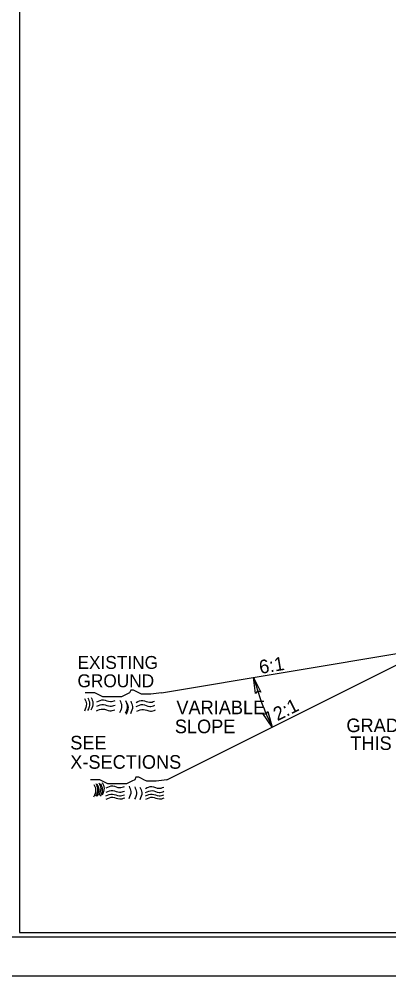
# Model space of a CAD drawing. Extents: x 2294370 to 2294957, y 719276 to 719941.
# Drawn here: x 2294488.5 to 2294531, y 719276.3 to 719386.3 of the extents above; entities that cross this region are included whole.
import ezdxf

# ---------------------------------------------------------------- set-up
doc = ezdxf.new("R2010")
doc.units = 0
for name, color, linetype in [('Old_Level_1', 7, 'Continuous'), ('Old_Level_11', 7, 'Continuous'), ('Old_Level_2', 7, 'Continuous'), ('Sheet Cutting Line CELL', 7, 'Continuous'), ('Sheet Plot Border Inside CELL', 7, 'Continuous'), ('Sheet Plot Border Outside CELL', 7, 'Continuous'), ('Sheet Typical CELL', 7, 'Continuous'), ('Typical Hinge Slope Arterial CELL', 7, 'Continuous')]:
    doc.layers.add(name, color=color, linetype=linetype)

msp = doc.modelspace()

# ---------------------------------------------------------------- linework, layer by layer
at = {"layer": 'Old_Level_11'}
for points in [[(2294515.69, 719308.79), (2294515.48, 719310.65), (2294516.31, 719308.96), (2294515.93, 719309.1)], [(2294517.12, 719306.75), (2294517.62, 719304.95), (2294516.53, 719306.49), (2294516.93, 719306.42)]]:
    msp.add_lwpolyline(points, close=True, dxfattribs=at)
at = {"layer": 'Old_Level_2'}
for points in [[(2294496.03, 719308.23), (2294496.24, 719307.61), (2294496.01, 719306.78)], [(2294496.03, 719308.23), (2294496.24, 719307.61), (2294496.01, 719306.78)], [(2294496.4, 719308.3), (2294496.61, 719307.68), (2294496.38, 719306.85)], [(2294496.4, 719308.3), (2294496.61, 719307.68), (2294496.38, 719306.85)], [(2294496.79, 719308.34), (2294497, 719307.72), (2294496.77, 719306.9)], [(2294496.79, 719308.34), (2294497, 719307.72), (2294496.77, 719306.9)], [(2294497.45, 719307.85), (2294498.2, 719308.07), (2294499, 719307.87), (2294499.57, 719308)], [(2294497.45, 719307.85), (2294498.2, 719308.07), (2294499, 719307.87), (2294499.57, 719308)], [(2294500.08, 719308.03), (2294500.29, 719307.41), (2294500.06, 719306.59)], [(2294500.08, 719308.03), (2294500.29, 719307.41), (2294500.06, 719306.59)], [(2294500.74, 719307.98), (2294500.95, 719307.36), (2294500.72, 719306.54)], [(2294500.74, 719307.98), (2294500.95, 719307.36), (2294500.72, 719306.54)], [(2294500.83, 719307.84), (2294501.04, 719307.22), (2294500.81, 719306.4)], [(2294501.34, 719307.93), (2294501.55, 719307.3), (2294501.32, 719306.48)], [(2294501.96, 719307.78), (2294502.72, 719308), (2294503.51, 719307.79), (2294504.08, 719307.92)], [(2294501.96, 719307.78), (2294502.72, 719308), (2294503.51, 719307.79), (2294504.08, 719307.92)], [(2294497.39, 719306.8), (2294498.14, 719307.02), (2294498.94, 719306.82), (2294499.51, 719306.94)], [(2294497.39, 719306.8), (2294498.14, 719307.02), (2294498.94, 719306.82), (2294499.51, 719306.94)], [(2294497.45, 719307.33), (2294498.2, 719307.54), (2294498.99, 719307.34), (2294499.56, 719307.47)], [(2294497.45, 719307.33), (2294498.2, 719307.54), (2294498.99, 719307.34), (2294499.56, 719307.47)], [(2294501.98, 719307.31), (2294502.74, 719307.53), (2294503.53, 719307.32), (2294504.1, 719307.45)], [(2294501.98, 719307.31), (2294502.74, 719307.53), (2294503.53, 719307.32), (2294504.1, 719307.45)], [(2294502.06, 719306.77), (2294502.81, 719306.98), (2294503.61, 719306.78), (2294504.18, 719306.91)], [(2294502.06, 719306.77), (2294502.81, 719306.98), (2294503.61, 719306.78), (2294504.18, 719306.91)], [(2294497.1, 719298.34), (2294497.31, 719297.72), (2294497.08, 719296.89)], [(2294497.32, 719298.44), (2294497.53, 719297.82), (2294497.3, 719297)], [(2294497.46, 719298.41), (2294497.67, 719297.78), (2294497.45, 719296.96)], [(2294497.68, 719298.52), (2294497.89, 719297.89), (2294497.66, 719297.07)], [(2294497.85, 719298.45), (2294498.07, 719297.83), (2294497.84, 719297)], [(2294498.07, 719298.56), (2294498.28, 719297.93), (2294498.05, 719297.11)], [(2294498.52, 719297.96), (2294499.27, 719298.18), (2294500.07, 719297.98), (2294500.64, 719298.11)], [(2294498.52, 719297.96), (2294499.27, 719298.18), (2294500.07, 719297.98), (2294500.64, 719298.11)], [(2294501.15, 719298.14), (2294501.36, 719297.52), (2294501.13, 719296.7)], [(2294501.15, 719298.14), (2294501.36, 719297.52), (2294501.13, 719296.7)], [(2294501.8, 719298.09), (2294502.01, 719297.47), (2294501.79, 719296.64)], [(2294501.8, 719298.09), (2294502.01, 719297.47), (2294501.79, 719296.64)], [(2294502.41, 719298.04), (2294502.62, 719297.41), (2294502.39, 719296.59)], [(2294502.41, 719298.04), (2294502.62, 719297.41), (2294502.39, 719296.59)], [(2294503.03, 719297.89), (2294503.78, 719298.11), (2294504.58, 719297.9), (2294505.15, 719298.03)], [(2294503.03, 719297.89), (2294503.78, 719298.11), (2294504.58, 719297.9), (2294505.15, 719298.03)], [(2294498.49, 719297.02), (2294499.24, 719297.24), (2294500.04, 719297.04), (2294500.61, 719297.17)], [(2294498.49, 719297.02), (2294499.24, 719297.24), (2294500.04, 719297.04), (2294500.61, 719297.17)], [(2294498.51, 719297.44), (2294499.27, 719297.65), (2294500.06, 719297.45), (2294500.63, 719297.58)], [(2294498.51, 719297.44), (2294499.27, 719297.65), (2294500.06, 719297.45), (2294500.63, 719297.58)], [(2294498.53, 719296.66), (2294499.28, 719296.88), (2294500.08, 719296.68), (2294500.65, 719296.8)], [(2294503.05, 719297.42), (2294503.8, 719297.64), (2294504.6, 719297.43), (2294505.17, 719297.56)], [(2294503.05, 719297.42), (2294503.8, 719297.64), (2294504.6, 719297.43), (2294505.17, 719297.56)], [(2294503.05, 719297.02), (2294503.8, 719297.24), (2294504.6, 719297.04), (2294505.17, 719297.17)], [(2294503.05, 719297.02), (2294503.8, 719297.24), (2294504.6, 719297.04), (2294505.17, 719297.17)], [(2294503.09, 719296.66), (2294503.84, 719296.88), (2294504.64, 719296.68), (2294505.21, 719296.8)]]:
    msp.add_spline(points, degree=3, dxfattribs=at)
at = {"layer": 'Sheet Cutting Line CELL'}
msp.add_line((2294455.16, 719276.34), (2294791.96, 719276.34), dxfattribs=at)
at = {"layer": 'Sheet Plot Border Inside CELL'}
msp.add_lwpolyline([(2294791.06, 719491.85), (2294457.76, 719491.85), (2294457.76, 719280.83), (2294791.06, 719280.83)], close=True, dxfattribs=at)
at = {"layer": 'Sheet Plot Border Outside CELL'}
for points in [[(2294455.16, 719276.34), (2294791.96, 719276.34), (2294791.96, 719496.34), (2294455.16, 719496.34)], [(2294791.96, 719496.34), (2294455.16, 719496.34), (2294455.16, 719276.34), (2294791.96, 719276.34)]]:
    msp.add_lwpolyline(points, close=True, dxfattribs=at)
at = {"layer": 'Sheet Typical CELL'}
msp.add_line((2294488.56, 719281.34), (2294488.56, 719281.34), dxfattribs=at)
msp.add_line((2294488.56, 719281.34), (2294488.56, 719281.34), dxfattribs=at)
msp.add_line((2294488.56, 719281.34), (2294488.56, 719281.34), dxfattribs=at)
msp.add_line((2294488.56, 719281.34), (2294488.56, 719281.34), dxfattribs=at)
msp.add_line((2294488.56, 719281.34), (2294488.56, 719281.34), dxfattribs=at)
msp.add_line((2294488.56, 719281.34), (2294488.56, 719281.34), dxfattribs=at)
msp.add_lwpolyline([(2294788.56, 719491.34), (2294488.56, 719491.34), (2294488.56, 719281.34), (2294788.56, 719281.34)], close=True, dxfattribs=at)
msp.add_lwpolyline([(2294496.06, 719281.34), (2294496.06, 719281.34)], dxfattribs=at)
at = {"layer": 'Typical Hinge Slope Arterial CELL'}
for p in [(2294504.9, 719308.89), (2294505.49, 719298.88)]:
    msp.add_line(p, (2294535.8, 719314.04), dxfattribs=at)
for points in [[(2294504.9, 719308.89), (2294503.67, 719308.73), (2294503.36, 719308.73), (2294502.9, 719308.73), (2294502.59, 719308.73), (2294502.28, 719308.89), (2294501.97, 719309.04), (2294501.66, 719309.2), (2294501.36, 719309.2), (2294501.2, 719308.89), (2294500.89, 719308.73), (2294500.59, 719308.58), (2294500.28, 719308.42), (2294499.97, 719308.42), (2294499.66, 719308.42), (2294499.35, 719308.42), (2294499.05, 719308.42), (2294498.74, 719308.42), (2294498.43, 719308.42), (2294498.12, 719308.42), (2294497.81, 719308.58), (2294497.51, 719308.73), (2294497.2, 719308.89), (2294496.74, 719308.89), (2294496.43, 719308.89), (2294496.12, 719308.89)], [(2294505.49, 719298.88), (2294504.26, 719298.73), (2294503.95, 719298.73), (2294503.49, 719298.73), (2294503.18, 719298.73), (2294502.87, 719298.88), (2294502.57, 719299.04), (2294502.26, 719299.19), (2294501.95, 719299.19), (2294501.8, 719298.88), (2294501.49, 719298.73), (2294501.18, 719298.58), (2294500.87, 719298.42), (2294500.56, 719298.42), (2294500.26, 719298.42), (2294499.95, 719298.42), (2294499.64, 719298.42), (2294499.33, 719298.42), (2294499.02, 719298.42), (2294498.72, 719298.42), (2294498.41, 719298.58), (2294498.1, 719298.73), (2294497.79, 719298.88), (2294497.33, 719298.88), (2294497.02, 719298.88), (2294496.71, 719298.88)]]:
    msp.add_lwpolyline(points, dxfattribs=at)
msp.add_arc((2294543.51, 719317.9), 28.94, 194.5, 206.5651, dxfattribs=at)

# ---------------------------------------------------------------- texts
at = {"layer": 'Old_Level_1'}
for s, height, rotation, p in [('EXISTING', 1.484, 360, (2294495.22, 719311.63)), ('6:1', 1.562, 9.4623, (2294516.25, 719311.05)), ('GROUND', 1.484, 360, (2294495.22, 719309.52)), ('2:1', 1.562, 26.5651, (2294518.23, 719305.61)), ('SEE ', 1.562, 360, (2294494.39, 719302.37)), ('X-SECTIONS', 1.562, 360, (2294494.39, 719300.15))]:
    msp.add_text(s, height=height, rotation=rotation, dxfattribs=at).set_placement(p)
at = {"layer": 'Old_Level_11'}
for s, p in [('GRADE TO', (2294526.16, 719304.36)), ('THIS LINE', (2294526.61, 719302.31))]:
    msp.add_text(s, height=1.562, rotation=0, dxfattribs=at).set_placement(p)
at = {"layer": 'Typical Hinge Slope Arterial CELL'}
for s, p in [('VARIABLE ', (2294506.6, 719306.42)), ('SLOPE', (2294506.42, 719304.24))]:
    msp.add_text(s, height=1.562, dxfattribs=at).set_placement(p)

doc.saveas('drawing.dxf')
